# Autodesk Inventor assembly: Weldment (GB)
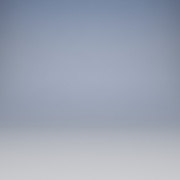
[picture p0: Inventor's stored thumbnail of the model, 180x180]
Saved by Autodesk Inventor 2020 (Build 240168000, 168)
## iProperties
Length Units: 11269
Angle Units: 11283
Time Units: 11279
Mass Units: 11290
Length Display Precision: 3
Angle Display Precision: 2
Part Number: Weldment (GB)
Document SubType Name: Weldment
Created: 2002-06
Designer: smithga
Created: 2002-08
Designer: F.Stasiak
Weld Material: Welded Aluminum-6061
Manager: www.cadconsulting.pl
Company: Fabian Stasiak CAD Consulting
Control State: 0
Master: False
Shininess: 64.0
Angle Units: 11279
Time Units: 11290
Mass Units: 11283
Compacted: True
Density: 0.0
Volumn: 0.0
Area: 0.0
PropertySet Name: Model Information
Author: F.Stasiak
Subject: Zbiór ćwiczeń. Autodesk Inventor 2020. Kurs podstawowy
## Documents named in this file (1)
- M:\AUTOBUILD\M24_168_RTM\Application\App\Templates\en-US\Metric\Weldment (GB).iam
